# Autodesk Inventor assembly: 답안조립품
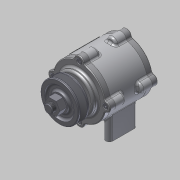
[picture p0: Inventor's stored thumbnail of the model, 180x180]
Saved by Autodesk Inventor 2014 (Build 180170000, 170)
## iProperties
Created: 2015-03
Part Number: 답안조립품
Document SubType Name: Assembly
Designer: MYHOME
Author: MYHOME
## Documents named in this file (11)
- C:\Documents and Settings\MYHOME\바탕 화면\450306V1020\답안조립품.iam
- C:\Documents and Settings\MYHOME\바탕 화면\450306V1020\본체.ipt
- C:\Documents and Settings\MYHOME\바탕 화면\450306V1020\커버.ipt
- C:\Documents and Settings\MYHOME\바탕 화면\450306V1020\커버2.ipt
- C:\Documents and Settings\MYHOME\바탕 화면\450306V1020\오일실.ipt
- C:\Documents and Settings\MYHOME\바탕 화면\450306V1020\M 4 x 12.ipt
- C:\Documents and Settings\MYHOME\바탕 화면\450306V1020\베어링 6204.ipt
- C:\Documents and Settings\MYHOME\바탕 화면\450306V1020\축.ipt
- C:\Documents and Settings\MYHOME\바탕 화면\450306V1020\키(4 x 4 x 12).ipt
- C:\Documents and Settings\MYHOME\바탕 화면\450306V1020\V벨트풀리.ipt
- C:\Documents and Settings\MYHOME\바탕 화면\450306V1020\너트 M12x1.25.ipt
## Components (14 placed, 6 different names)
1. KS B 2804 D D - 20 32 8:1
2. KS B 2023 6204 - 20 x 47 x 14:1 — 각도:1
3. KS B 2023 6204 - 20 x 47 x 14:2 — 각도:2
4. KS B 1311 (I) 4 x 4 x 12:1
5. 그루브 풀리1:1
6. KS B 1012 클래스 1 일반 - 미터 M12x1.25:1 — 각도:3
7. KS B 1003 - 미터 M 4 x 12:1
8. KS B 1003 - 미터 M 4 x 12:2
9. KS B 1003 - 미터 M 4 x 12:3
10. KS B 1003 - 미터 M 4 x 12:4
11. KS B 1003 - 미터 M 4 x 12:5
12. KS B 1003 - 미터 M 4 x 12:6
13. KS B 1003 - 미터 M 4 x 12:7
14. KS B 1003 - 미터 M 4 x 12:8
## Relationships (3: Angle 3)
- 각도:1 [Angle]: KS B 2023 6204 - 20 x 47 x 14:1
- 각도:2 [Angle]: KS B 2023 6204 - 20 x 47 x 14:2
- 각도:3 [Angle]: KS B 1012 클래스 1 일반 - 미터 M12x1.25:1
